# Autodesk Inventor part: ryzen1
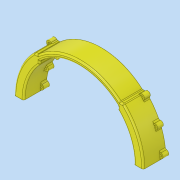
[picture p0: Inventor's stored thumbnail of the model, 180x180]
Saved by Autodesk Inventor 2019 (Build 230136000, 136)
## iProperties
Created: 2022-03
Part Number: ryzen1
Material: Типовые
Document SubType Name: Modeling
Designer: mitof
Density: 1 g/cm^3
Appearance: Желтый
Author: mitof
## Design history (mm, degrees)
sketch "Эскиз1"
  geometry: L1 (-80, 0)-(-74, 0); L2 (74, 0)-(80, 0); A1 r 80 centre (0, 0) between (80, 0) and (-80, 0); A2 r 74 centre (0, 0) between (74, 0) and (-74, 0); 1 further point
  constraints: 4 end point, 4 point on circle, 2 centre point, 2 point on line, 1 coincident, 1 horizontal
  dimensions: "d0" = 160 diameter of A1; "d1" = 6 radial gap between concentric circles of A1 A2
extrude "Выдавливание1" new body sketch "Эскиз1" distance "d2" = 26.5; taper "d3" = 0 deg
sketch "Эскиз2"
  geometry: L1 (-57.35, 60)-(-52.915, 60); L2 (-50.408, 54.176)-(-50.408, 50); L3 (52.915, 60)-(57.35, 60); L4 (50.408, 54.176)-(50.408, 50); L5 (-74, 0)-(-80, 0) reference; L6 (-83, 0)-(-80, 0); L7 (-80, 0)-(-74, 0); L8 (-74, 0)-(-71, 0); L9 (71, 0)-(74, 0); L10 (80, 0)-(74, 0) reference; L11 (80, 0)-(83, 0); A1 r 74 centre (0, 0) between (74, 0) and (-74, 0) reference; A2 r 80 centre (0, 0) between (80, 0) and (-80, 0) reference; A3 r 80 centre (0, 0) between (80, 0) and (-80, 0) reference; A4 r 74 centre (0, 0) between (74, 0) and (-74, 0) reference; A5 r 83 centre (0, 0) between (83, 0) and (57.35, 60); A6 r 83 centre (0, 0) between (-57.35, 60) and (-83, 0); A7 r 71 centre (0, 0) between (71, 0) and (50.408, 50); A8 r 71 centre (0, 0) between (-50.408, 50) and (-71, 0); 1 further point
  constraints: 18 end point, 12 point on circle, 5 collinear, 4 centre point, 2 horizontal, 2 perpendicular
  dimensions: "d6" = 50 vertical distance of point (0, 0) L2.end; "d7" = 60 vertical distance of point (0, 0) L1.start
extrude "Выдавливание2" join sketch "Эскиз2" stored distance "d8" = 35; taper "d9" = 0 deg
sketch "Эскиз3"
  geometry: L1 (-54.254, 50.617)-(-58.347, 54.439); L2 (54.254, 50.617)-(58.347, 54.439); L3 (-79.8, 0)-(-74.2, 0); L4 (-83, 0)-(-71, 0) reference; L5 (74.2, 0)-(79.8, 0); L6 (71, 0)-(83, 0) reference; A1 r 83 centre (0, 0) between (-57.35, 60) and (-83, 0) reference; A2 r 71 centre (0, 0) between (-50.408, 50) and (-71, 0) reference; A3 r 71 centre (0, 0) between (71, 0) and (50.408, 50) reference; A4 r 83 centre (0, 0) between (83, 0) and (57.35, 60) reference; A5 r 74.2 centre (0, 0) between (74.2, 0) and (54.254, 50.617); A6 r 79.8 centre (0, 0) between (79.8, 0) and (58.347, 54.439); A7 r 74.2 centre (0, 0) between (-54.254, 50.617) and (-74.2, 0); A8 r 79.8 centre (0, 0) between (-58.347, 54.439) and (-79.8, 0); 1 further point
  constraints: 8 end point, 8 point on circle, 4 centre point, 2 collinear
  dimensions: "d10" = 3.2 radial gap between concentric circles of A3 A5; "d11" = 3.2 radial gap between concentric circles of A4 A6; "d12" = 3.2 radial gap between concentric circles of A2 A7; "d13" = 3.2 radial gap between concentric circles of A1 A8
extrude "Выдавливание3" cut sketch "Эскиз3" distance "d14" = 21; taper "d15" = 0 deg
sketch "Эскиз4"
  geometry: L1 (54.254, 50.617)-(58.347, 54.439) reference; L2 (-58.347, 54.439)-(-54.254, 50.617) reference; A1 r 80 centre (0, 0) between (52.915, 60) and (-52.915, 60) reference; A2 r 74 centre (0, 0) between (50.408, 54.176) and (-50.408, 54.176) reference; A3 r 78 centre (0, 0) between (57.032, 53.211) and (-57.032, 53.211); A4 r 76 centre (0, 0) between (55.57, 51.846) and (-55.57, 51.846); 1 further point
  constraints: 4 point on circle, 4 point on line, 2 centre point
  dimensions: "d16" = 2 radial gap between concentric circles of A1 A3; "d17" = 2 radial gap between concentric circles of A2 A4
extrude "Выдавливание4" cut sketch "Эскиз4" distance "d18" = 5; taper "d19" = 0 deg
fillet "Сопряжение1" dims "d20" = 2
sketch "Эскиз5"
  geometry: C1 r 1.35 at (70, 5); C2 r 3.35 at (70, 5); 1 further point
  constraints: 2 centre point
  dimensions: "d21" = 2.7 diameter of C1; "d22" = 70 horizontal distance of C1.centre point (0, 0); "d23" = 5 vertical distance of point (0, 0) C1.centre; "d24" = 2 radial gap between concentric circles of C1 C2
extrude "Выдавливание5" join sketch "Эскиз5" distance "d25" = 5; taper "d26" = 0 deg
sketch "Эскиз6"
  geometry: C1 r 1.35 at (70, 5); A1 r 1.35 centre (70, 5) between (70.735, 6.133) and (70.888, 3.983) reference; 1 further point
  constraints: 1 centre point, 1 coincident
extrude "Выдавливание6" cut sketch "Эскиз6" distance "d27" = 5; taper "d28" = 0 deg
pattern_circular "Круговой массив1" dims angle "d30" = 40 deg
sketch "Эскиз7"
  geometry: C1 r 1.35 at (0, 73); A1 r 76 centre (0, 0) between (55.57, 51.846) and (-55.57, 51.846) reference; A2 r 3.35 centre (0, 73) between (-1.521, 75.985) and (1.521, 75.985); 1 further point
  constraints: 4 point on circle, 2 centre point
  dimensions: "d32" = 2.7 diameter of C1; "d33" = 73 distance of A1.centre C1.centre; "d34" = 2 radial gap between concentric circles of C1 A2
extrude "Выдавливание7" join sketch "Эскиз7" distance "d35" = 5; taper "d36" = 0 deg
sketch "Эскиз8"
  geometry: C1 r 1.35 at (0, 73); A1 r 1.35 centre (0, 73) between (-0.913, 73.994) and (0.913, 73.994) reference; 1 further point
  constraints: 1 centre point, 1 coincident
extrude "Выдавливание8" cut sketch "Эскиз8" distance "d37" = 5; taper "d38" = 0 deg
mirror "Зеркальное отражение1"
fillet "Сопряжение2" dims "d39" = 2
chamfer "Фаска1" distance "d40" = 8; stored, may be unused: second distance "d41" = 2, angle "d42" = 45 deg
chamfer "Фаска2" distance "d43" = 8; stored, may be unused: second distance "d44" = 2, angle "d45" = 45 deg
sketch "Эскиз11"
  geometry: C1 r 1.35 at (-70, 5) reference; C2 r 1.35 at (-64.068, 28.64) reference; C3 r 1.35 at (-50.409, 48.825) reference; C4 r 1.35 at (-83.5, 5); C5 r 1.35 at (-76.568, 33.925); C6 r 1.35 at (-59.809, 58.536); C7 r 3.35 at (-83.5, 5); C8 r 3.35 at (-76.568, 33.925); C9 r 3.35 at (-59.809, 58.536); A1 r 83 centre (0, 0) between (-57.938, 59.432) and (-83, 0) reference; 1 further point
  constraints: 6 centre point
  dimensions: "d46" = 2.7 diameter of C4; "d47" = 13.5 distance of C1.centre C4.centre; "d48" = 2.7 diameter of C5; "d49" = 12.5 horizontal distance of C2.centre C5.centre; "d50" = 2.7 diameter of C6; "d51" = 9.4 horizontal distance of C3.centre C6.centre; "d52" = 2 radial gap between concentric circles of C4 C7; "d53" = 2 radial gap between concentric circles of C5 C8; "d54" = 2 radial gap between concentric circles of C6 C9
extrude "Выдавливание9" join sketch "Эскиз11" distance "d55" = 5; taper "d56" = 0 deg
sketch "Эскиз12"
  geometry: C1 r 1.35 at (-83.5, 5); A1 r 1.35 centre (-83.5, 5) between (-82.773, 6.137) and (-82.914, 3.784) reference; A2 r 1.35 centre (-76.568, 33.925) between (-75.425, 34.643) and (-76.331, 32.596) reference; A3 r 1.35 centre (-59.809, 58.536) between (-58.503, 58.876) and (-60.122, 57.222) reference; 3 further points
  constraints: 3 coincident, 1 centre point, 6 other
extrude "Выдавливание10" cut sketch "Эскиз12" distance "d57" = 5; taper "d58" = 0 deg
sketch "Эскиз13"
  geometry: L1 (-83, 0)-(-79.8, 0) reference; L2 (-58.347, 54.439)-(-57.032, 53.211) reference; L3 (57.032, 53.211)-(58.347, 54.439) reference; L4 (79.8, 0)-(83, 0) reference; L5 (56.542, 60)-(53.666, 60) reference; L6 (-53.666, 60)-(-56.542, 60) reference; C1 r 1.35 at (0, 73) reference; C2 r 1.35 at (-76.568, 33.925) reference; C3 r 1.35 at (-83.5, 5) reference; C4 r 1.35 at (-59.809, 58.536) reference; A1 r 1.35 centre (0, 81) between (0.901, 79.995) and (-0.901, 79.995); A2 r 3.35 centre (0, 81) between (3.177, 79.937) and (-3.177, 79.937); A3 r 3.35 centre (-59.809, 58.536) between (-56.789, 59.985) and (-61.556, 55.677) reference; A4 r 83 centre (0, 0) between (-61.556, 55.677) and (-74.51, 36.569) reference; A5 r 3.35 centre (-76.568, 33.925) between (-74.51, 36.569) and (-77.143, 30.625) reference; A6 r 83 centre (0, 0) between (-77.143, 30.625) and (-82.592, 8.224) reference; A7 r 3.35 centre (-83.5, 5) between (-82.592, 8.224) and (-82.983, 1.69) reference; A8 r 83 centre (0, 0) between (-82.983, 1.69) and (-83, 0) reference; A9 r 79.8 centre (0, 0) between (-58.347, 54.439) and (-79.8, 0) reference; A10 r 78 centre (0, 0) between (57.032, 53.211) and (-57.032, 53.211) reference; A11 r 79.8 centre (0, 0) between (79.8, 0) and (58.347, 54.439) reference; A12 r 83 centre (0, 0) between (83, 0) and (57.938, 59.432) reference; A13 r 2 centre (56.542, 58) between (57.938, 59.432) and (56.542, 60) reference; A14 r 2 centre (53.666, 62) between (52.357, 60.488) and (53.666, 60) reference; A15 r 80 centre (0, 0) between (52.357, 60.488) and (-52.357, 60.488) reference; A16 r 2 centre (-53.666, 62) between (-53.666, 60) and (-52.357, 60.488) reference; A17 r 2 centre (-56.542, 58) between (-56.542, 60) and (-56.789, 59.985) reference; 1 further point
  constraints: 8 point on circle, 2 centre point
  dimensions: "d59" = 2.7 diameter of A1; "d60" = 8 distance of C1.centre A1.centre; "d61" = 2 radial gap between concentric circles of A1 A2
extrude "Выдавливание11" join sketch "Эскиз13" distance "d62" = 5; taper "d63" = 0 deg
sketch "Эскиз14"
  geometry: C1 r 1.35 at (0, 81); A1 r 1.35 centre (0, 81) between (0.901, 79.995) and (-0.901, 79.995) reference; 1 further point
  constraints: 1 centre point, 1 coincident
extrude "Выдавливание12" cut sketch "Эскиз14" distance "d64" = 5; taper "d65" = 0 deg
fillet "Сопряжение3" dims "d66" = 2
mirror "Зеркальное отражение2"
fillet "Сопряжение4" dims "d67" = 2
sketch "Эскиз15"
  geometry: L1 (71, 0)-(74.2, 0) reference; L2 (54.254, 50.617)-(55.57, 51.846) reference; L3 (-55.57, 51.846)-(-54.254, 50.617) reference; L4 (-74.2, 0)-(-71, 0) reference; L5 (55.732, 60)-(53.666, 60) reference; L6 (-53.666, 60)-(-55.732, 60) reference; L7 (-83, 0)-(-79.8, 0) reference; L8 (-58.347, 54.439)-(-57.032, 53.211) reference; L9 (57.032, 53.211)-(58.347, 54.439) reference; L10 (79.8, 0)-(83, 0) reference; C1 r 1.35 at (0, 73) reference; C2 r 1.35 at (64.068, 28.64) reference; C3 r 1.35 at (70, 5) reference; C4 r 1.35 at (50.409, 48.825) reference; C5 r 1.35 at (-70, 5) reference; C6 r 1.35 at (-50.409, 48.825) reference; C7 r 1.35 at (-64.068, 28.64) reference; C8 r 1.35 at (76.568, 33.925) reference; C9 r 1.35 at (0, 81) reference; C10 r 1.35 at (-76.568, 33.925) reference; C11 r 1.35 at (-83.5, 5) reference; C12 r 1.35 at (-59.809, 58.536) reference; C13 r 1.35 at (83.5, 5) reference; C14 r 1.35 at (59.809, 58.536) reference; A1 r 3.35 centre (-50.409, 48.825) between (-52.045, 45.902) and (-49.156, 51.932) reference; A2 r 2 centre (-48.408, 53.787) between (-50.393, 53.542) and (-49.156, 51.932) reference; A3 r 2 centre (-48.408, 53.298) between (-49.753, 54.778) and (-50.393, 53.542) reference; A4 r 74 centre (0, 0) between (-5.361, 73.806) and (-49.753, 54.778) reference; A5 r 2 centre (-5.216, 71.811) between (-3.266, 72.255) and (-5.361, 73.806) reference; A6 r 3.35 centre (0, 73) between (-3.266, 72.255) and (3.266, 72.255) reference; A7 r 2 centre (5.216, 71.811) between (5.361, 73.806) and (3.266, 72.255) reference; A8 r 74 centre (0, 0) between (49.753, 54.778) and (5.361, 73.806) reference; A9 r 2 centre (48.408, 53.298) between (50.393, 53.542) and (49.753, 54.778) reference; A10 r 2 centre (48.408, 53.787) between (49.156, 51.932) and (50.393, 53.542) reference; A11 r 3.35 centre (50.409, 48.825) between (49.156, 51.932) and (52.045, 45.902) reference; A12 r 2 centre (53.021, 44.156) between (54.558, 45.436) and (52.045, 45.902) reference; A13 r 71 centre (0, 0) between (62.465, 33.751) and (54.558, 45.436) reference; A14 r 2 centre (60.705, 32.801) between (61.962, 31.245) and (62.465, 33.751) reference; A15 r 3.35 centre (64.068, 28.64) between (61.962, 31.245) and (64.605, 25.333) reference; A16 r 2 centre (64.926, 23.359) between (66.808, 24.036) and (64.605, 25.333) reference; A17 r 71 centre (0, 0) between (70.241, 10.352) and (66.808, 24.036) reference; A18 r 2 centre (68.263, 10.06) between (68.912, 8.168) and (70.241, 10.352) reference; A19 r 3.35 centre (70, 5) between (68.912, 8.168) and (69.384, 1.707) reference; A20 r 2 centre (69.017, -0.259) between (71, 0) and (69.384, 1.707) reference; A21 r 74.2 centre (0, 0) between (74.2, 0) and (54.254, 50.617) reference; A22 r 76 centre (0, 0) between (55.57, 51.846) and (-55.57, 51.846) reference; A23 r 74.2 centre (0, 0) between (-54.254, 50.617) and (-74.2, 0) reference; A24 r 2 centre (-69.017, -0.259) between (-69.384, 1.707) and (-71, 0) reference; A25 r 3.35 centre (-70, 5) between (-69.384, 1.707) and (-68.912, 8.168) reference; A26 r 2 centre (-68.263, 10.06) between (-70.241, 10.352) and (-68.912, 8.168) reference; A27 r 71 centre (0, 0) between (-66.808, 24.036) and (-70.241, 10.352) reference; A28 r 2 centre (-64.926, 23.359) between (-64.605, 25.333) and (-66.808, 24.036) reference; A29 r 3.35 centre (-64.068, 28.64) between (-64.605, 25.333) and (-61.962, 31.245) reference; A30 r 2 centre (-60.705, 32.801) between (-62.465, 33.751) and (-61.962, 31.245) reference; A31 r 71 centre (0, 0) between (-54.558, 45.436) and (-62.465, 33.751) reference; A32 r 2 centre (-53.021, 44.156) between (-52.045, 45.902) and (-54.558, 45.436) reference; A33 r 2 centre (53.666, 62) between (52.357, 60.488) and (53.666, 60) reference; A34 r 80 centre (0, 0) between (52.357, 60.488) and (5.156, 79.834) reference; A35 r 2 centre (5.285, 81.829) between (3.309, 81.519) and (5.156, 79.834) reference; A36 r 3.35 centre (0, 81) between (3.309, 81.519) and (-3.309, 81.519) reference; A37 r 2 centre (-5.285, 81.829) between (-5.156, 79.834) and (-3.309, 81.519) reference; A38 r 80 centre (0, 0) between (-5.156, 79.834) and (-52.357, 60.488) reference; A39 r 2 centre (-53.666, 62) between (-53.666, 60) and (-52.357, 60.488) reference; A40 r 2 centre (-55.732, 62) between (-57.256, 60.705) and (-55.732, 60) reference; A41 r 3.35 centre (-59.809, 58.536) between (-57.256, 60.705) and (-62.613, 56.702) reference; A42 r 2 centre (-64.287, 55.608) between (-62.774, 54.299) and (-62.613, 56.702) reference; A43 r 83 centre (0, 0) between (-62.774, 54.299) and (-73.669, 38.235) reference; A44 r 2 centre (-75.444, 39.156) between (-75.864, 37.201) and (-73.669, 38.235) reference; A45 r 3.35 centre (-76.568, 33.925) between (-75.864, 37.201) and (-78.521, 31.204) reference; A46 r 2 centre (-79.687, 29.579) between (-77.812, 28.883) and (-78.521, 31.204) reference; A47 r 83 centre (0, 0) between (-77.812, 28.883) and (-82.391, 10.036) reference; A48 r 2 centre (-84.376, 10.278) between (-84.049, 8.305) and (-82.391, 10.036) reference; A49 r 3.35 centre (-83.5, 5) between (-84.049, 8.305) and (-84.436, 1.784) reference; A50 r 2 centre (-84.995, -0.137) between (-83, 0) and (-84.436, 1.784) reference; A51 r 79.8 centre (0, 0) between (-58.347, 54.439) and (-79.8, 0) reference; A52 r 78 centre (0, 0) between (57.032, 53.211) and (-57.032, 53.211) reference; A53 r 79.8 centre (0, 0) between (79.8, 0) and (58.347, 54.439) reference; A54 r 2 centre (84.995, -0.137) between (84.436, 1.784) and (83, 0) reference; A55 r 3.35 centre (83.5, 5) between (84.436, 1.784) and (84.049, 8.305) reference; A56 r 2 centre (84.376, 10.278) between (82.391, 10.036) and (84.049, 8.305) reference; A57 r 83 centre (0, 0) between (82.391, 10.036) and (77.812, 28.883) reference; A58 r 2 centre (79.687, 29.579) between (78.521, 31.204) and (77.812, 28.883) reference; A59 r 3.35 centre (76.568, 33.925) between (78.521, 31.204) and (75.864, 37.201) reference; A60 r 2 centre (75.444, 39.156) between (73.669, 38.235) and (75.864, 37.201) reference; A61 r 83 centre (0, 0) between (73.669, 38.235) and (62.774, 54.299) reference; A62 r 2 centre (64.287, 55.608) between (62.613, 56.702) and (62.774, 54.299) reference; A63 r 3.35 centre (59.809, 58.536) between (62.613, 56.702) and (57.256, 60.705) reference; A64 r 2 centre (55.732, 62) between (55.732, 60) and (57.256, 60.705) reference; 1 further point
extrude "Выдавливание13" join sketch "Эскиз15" distance "d68" = 2.4; taper "d69" = 0 deg
sketch "Эскиз16"
  geometry: L1 (79.8, 0)-(74.2, 0) reference; L2 (54.254, 50.617)-(58.347, 54.439) reference; L3 (55.812, 48.895)-(60.024, 52.585); L4 (57.316, 47.122)-(61.642, 50.678); A1 r 79.8 centre (0, 0) between (79.8, 0) and (58.347, 54.439) reference; A2 r 74.2 centre (0, 0) between (74.2, 0) and (54.254, 50.617) reference; A3 r 79.8 centre (0, 0) between (79.8, 0) and (58.347, 54.439) reference; 1 further point
  constraints: 4 end point, 4 point on circle
  dimensions: "d70" = 2.5 distance from line of L2 L3.end; "d71" = 2.5 distance from line of L3 L4.end
extrude "Выдавливание14" cut sketch "Эскиз16" distance "d72" = 1.2; taper "d73" = 0 deg
fillet "Сопряжение5" dims "d74" = 1.2
fillet "Сопряжение6" dims "d75" = 0.4
pattern_circular "Круговой массив2" dims angle "d77" = 37 deg
fillet "Сопряжение7" dims "d79" = 0.4
mirror "Зеркальное отражение3"
fillet "Сопряжение8" dims "d80" = 0.4
sketch "Эскиз18"
  geometry: L1 (55.732, 60)-(53.666, 60) reference; L2 (-53.666, 60)-(-55.732, 60) reference; L3 (-83, 0)-(-79.8, 0) reference; L4 (-58.347, 54.439)-(-57.032, 53.211) reference; L5 (57.032, 53.211)-(58.347, 54.439) reference; L6 (79.8, 0)-(83, 0) reference; L7 (71, 0)-(74.2, 0) reference; L8 (54.254, 50.617)-(55.57, 51.846) reference; L9 (-55.57, 51.846)-(-54.254, 50.617) reference; L10 (-74.2, 0)-(-71, 0) reference; L11 (-74.6, 0)-(-74.2, 0); L12 (-79.4, 0)-(-79.8, 0); L13 (-81, 0)-(-73, 0) reference; L14 (-58.347, 54.439)-(-54.254, 50.617) reference; L15 (-54.547, 50.89)-(-54.254, 50.617); L16 (-58.055, 54.166)-(-58.347, 54.439); C1 r 1.35 at (59.809, 58.536) reference; C2 r 1.35 at (83.5, 5) reference; C3 r 1.35 at (-59.809, 58.536) reference; C4 r 1.35 at (-83.5, 5) reference; C5 r 1.35 at (-76.568, 33.925) reference; C6 r 1.35 at (0, 81) reference; C7 r 1.35 at (76.568, 33.925) reference; C8 r 1.35 at (-64.068, 28.64) reference; C9 r 1.35 at (-50.409, 48.825) reference; C10 r 1.35 at (-70, 5) reference; C11 r 1.35 at (50.409, 48.825) reference; C12 r 1.35 at (70, 5) reference; C13 r 1.35 at (64.068, 28.64) reference; C14 r 1.35 at (0, 73) reference; A1 r 2 centre (53.666, 62) between (52.357, 60.488) and (53.666, 60) reference; A2 r 80 centre (0, 0) between (52.357, 60.488) and (5.156, 79.834) reference; A3 r 2 centre (5.285, 81.829) between (3.309, 81.519) and (5.156, 79.834) reference; A4 r 3.35 centre (0, 81) between (3.309, 81.519) and (-3.309, 81.519) reference; A5 r 2 centre (-5.285, 81.829) between (-5.156, 79.834) and (-3.309, 81.519) reference; A6 r 80 centre (0, 0) between (-5.156, 79.834) and (-52.357, 60.488) reference; A7 r 2 centre (-53.666, 62) between (-53.666, 60) and (-52.357, 60.488) reference; A8 r 2 centre (-55.732, 62) between (-57.256, 60.705) and (-55.732, 60) reference; A9 r 3.35 centre (-59.809, 58.536) between (-57.256, 60.705) and (-62.613, 56.702) reference; A10 r 2 centre (-64.287, 55.608) between (-62.774, 54.299) and (-62.613, 56.702) reference; A11 r 83 centre (0, 0) between (-62.774, 54.299) and (-73.669, 38.235) reference; A12 r 2 centre (-75.444, 39.156) between (-75.864, 37.201) and (-73.669, 38.235) reference; A13 r 3.35 centre (-76.568, 33.925) between (-75.864, 37.201) and (-78.521, 31.204) reference; A14 r 2 centre (-79.687, 29.579) between (-77.812, 28.883) and (-78.521, 31.204) reference; A15 r 83 centre (0, 0) between (-77.812, 28.883) and (-82.391, 10.036) reference; A16 r 2 centre (-84.376, 10.278) between (-84.049, 8.305) and (-82.391, 10.036) reference; A17 r 3.35 centre (-83.5, 5) between (-84.049, 8.305) and (-84.436, 1.784) reference; A18 r 2 centre (-84.995, -0.137) between (-83, 0) and (-84.436, 1.784) reference; A19 r 79.8 centre (0, 0) between (-58.347, 54.439) and (-79.8, 0) reference; A20 r 78 centre (0, 0) between (57.032, 53.211) and (-57.032, 53.211) reference; A21 r 79.8 centre (0, 0) between (79.8, 0) and (58.347, 54.439) reference; A22 r 2 centre (84.995, -0.137) between (84.436, 1.784) and (83, 0) reference; A23 r 3.35 centre (83.5, 5) between (84.436, 1.784) and (84.049, 8.305) reference; A24 r 2 centre (84.376, 10.278) between (82.391, 10.036) and (84.049, 8.305) reference; A25 r 83 centre (0, 0) between (82.391, 10.036) and (77.812, 28.883) reference; A26 r 2 centre (79.687, 29.579) between (78.521, 31.204) and (77.812, 28.883) reference; A27 r 3.35 centre (76.568, 33.925) between (78.521, 31.204) and (75.864, 37.201) reference; A28 r 2 centre (75.444, 39.156) between (73.669, 38.235) and (75.864, 37.201) reference; A29 r 83 centre (0, 0) between (73.669, 38.235) and (62.774, 54.299) reference; A30 r 2 centre (64.287, 55.608) between (62.613, 56.702) and (62.774, 54.299) reference; A31 r 3.35 centre (59.809, 58.536) between (62.613, 56.702) and (57.256, 60.705) reference; A32 r 2 centre (55.732, 62) between (55.732, 60) and (57.256, 60.705) reference; A33 r 3.35 centre (-50.409, 48.825) between (-52.045, 45.902) and (-49.156, 51.932) reference; A34 r 2 centre (-48.408, 53.787) between (-50.393, 53.542) and (-49.156, 51.932) reference; A35 r 2 centre (-48.408, 53.298) between (-49.753, 54.778) and (-50.393, 53.542) reference; A36 r 74 centre (0, 0) between (-5.361, 73.806) and (-49.753, 54.778) reference; A37 r 2 centre (-5.216, 71.811) between (-3.266, 72.255) and (-5.361, 73.806) reference; A38 r 3.35 centre (0, 73) between (-3.266, 72.255) and (3.266, 72.255) reference; A39 r 2 centre (5.216, 71.811) between (5.361, 73.806) and (3.266, 72.255) reference; A40 r 74 centre (0, 0) between (49.753, 54.778) and (5.361, 73.806) reference; A41 r 2 centre (48.408, 53.298) between (50.393, 53.542) and (49.753, 54.778) reference; A42 r 2 centre (48.408, 53.787) between (49.156, 51.932) and (50.393, 53.542) reference; A43 r 3.35 centre (50.409, 48.825) between (49.156, 51.932) and (52.045, 45.902) reference; A44 r 2 centre (53.021, 44.156) between (54.558, 45.436) and (52.045, 45.902) reference; A45 r 71 centre (0, 0) between (62.465, 33.751) and (54.558, 45.436) reference; A46 r 2 centre (60.705, 32.801) between (61.962, 31.245) and (62.465, 33.751) reference; A47 r 3.35 centre (64.068, 28.64) between (61.962, 31.245) and (64.605, 25.333) reference; A48 r 2 centre (64.926, 23.359) between (66.808, 24.036) and (64.605, 25.333) reference; A49 r 71 centre (0, 0) between (70.241, 10.352) and (66.808, 24.036) reference; A50 r 2 centre (68.263, 10.06) between (68.912, 8.168) and (70.241, 10.352) reference; A51 r 3.35 centre (70, 5) between (68.912, 8.168) and (69.384, 1.707) reference; A52 r 2 centre (69.017, -0.259) between (71, 0) and (69.384, 1.707) reference; A53 r 74.2 centre (0, 0) between (74.2, 0) and (54.254, 50.617) reference; A54 r 76 centre (0, 0) between (55.57, 51.846) and (-55.57, 51.846) reference; A55 r 74.2 centre (0, 0) between (-54.254, 50.617) and (-74.2, 0) reference; A56 r 2 centre (-69.017, -0.259) between (-69.384, 1.707) and (-71, 0) reference; A57 r 3.35 centre (-70, 5) between (-69.384, 1.707) and (-68.912, 8.168) reference; A58 r 2 centre (-68.263, 10.06) between (-70.241, 10.352) and (-68.912, 8.168) reference; A59 r 71 centre (0, 0) between (-66.808, 24.036) and (-70.241, 10.352) reference; A60 r 2 centre (-64.926, 23.359) between (-64.605, 25.333) and (-66.808, 24.036) reference; A61 r 3.35 centre (-64.068, 28.64) between (-64.605, 25.333) and (-61.962, 31.245) reference; A62 r 2 centre (-60.705, 32.801) between (-62.465, 33.751) and (-61.962, 31.245) reference; A63 r 71 centre (0, 0) between (-54.558, 45.436) and (-62.465, 33.751) reference; A64 r 2 centre (-53.021, 44.156) between (-52.045, 45.902) and (-54.558, 45.436) reference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; 1 further point
  constraints: 8 end point, 4 point on circle, 3 collinear, 2 centre point, 1 horizontal
  dimensions: "d81" = 0.4 radial gap between concentric circles of A19 A67; "d82" = 0.4 radial gap between concentric circles of A55 A68
extrude "Выдавливание15" join sketch "Эскиз18" stored distance "d83" = 10; taper "d84" = 0 deg
sketch "Эскиз19"
  geometry: L1 (55.732, 60)-(53.666, 60) reference; L2 (-53.666, 60)-(-55.732, 60) reference; L3 (-83, 0)-(-79.4, 0) reference; L4 (-58.055, 54.166)-(-57.032, 53.211) reference; L5 (57.032, 53.211)-(58.347, 54.439) reference; L6 (79.8, 0)-(83, 0) reference; L7 (71, 0)-(74.2, 0) reference; L8 (54.254, 50.617)-(55.57, 51.846) reference; L9 (-55.57, 51.846)-(-54.547, 50.89) reference; L10 (-74.6, 0)-(-71, 0) reference; L11 (79.4, 0)-(79.8, 0); L12 (57.032, 53.211)-(58.347, 54.439) reference; L13 (58.055, 54.166)-(58.347, 54.439); L14 (54.254, 50.617)-(55.57, 51.846) reference; L15 (58.62, 54.147)-(58.619, 54.146); L16 (79.799, 0.4)-(79.8, 0.4); L17 (58.619, 54.146)-(58.347, 54.439); L18 (79.8, 0.4)-(79.8, 0); L19 (74.2, 0)-(74.6, 0); L20 (54.547, 50.89)-(54.254, 50.617); C1 r 1.35 at (59.809, 58.536) reference; C2 r 1.35 at (83.5, 5) reference; C3 r 1.35 at (-59.809, 58.536) reference; C4 r 1.35 at (-83.5, 5) reference; C5 r 1.35 at (-76.568, 33.925) reference; C6 r 1.35 at (0, 81) reference; C7 r 1.35 at (76.568, 33.925) reference; C8 r 1.35 at (-64.068, 28.64) reference; C9 r 1.35 at (-50.409, 48.825) reference; C10 r 1.35 at (-70, 5) reference; C11 r 1.35 at (50.409, 48.825) reference; C12 r 1.35 at (70, 5) reference; C13 r 1.35 at (64.068, 28.64) reference; C14 r 1.35 at (0, 73) reference; A1 r 79.8 centre (0, 0) between (79.8, 0) and (58.347, 54.439) reference; A2 r 74.2 centre (0, 0) between (74.2, 0) and (54.254, 50.617) reference; A3 r 2 centre (53.666, 62) between (52.357, 60.488) and (53.666, 60) reference; A4 r 80 centre (0, 0) between (52.357, 60.488) and (5.156, 79.834) reference; A5 r 2 centre (5.285, 81.829) between (3.309, 81.519) and (5.156, 79.834) reference; A6 r 3.35 centre (0, 81) between (3.309, 81.519) and (-3.309, 81.519) reference; A7 r 2 centre (-5.285, 81.829) between (-5.156, 79.834) and (-3.309, 81.519) reference; A8 r 80 centre (0, 0) between (-5.156, 79.834) and (-52.357, 60.488) reference; A9 r 2 centre (-53.666, 62) between (-53.666, 60) and (-52.357, 60.488) reference; A10 r 2 centre (-55.732, 62) between (-57.256, 60.705) and (-55.732, 60) reference; A11 r 3.35 centre (-59.809, 58.536) between (-57.256, 60.705) and (-62.613, 56.702) reference; A12 r 2 centre (-64.287, 55.608) between (-62.774, 54.299) and (-62.613, 56.702) reference; A13 r 83 centre (0, 0) between (-62.774, 54.299) and (-73.669, 38.235) reference; A14 r 2 centre (-75.444, 39.156) between (-75.864, 37.201) and (-73.669, 38.235) reference; A15 r 3.35 centre (-76.568, 33.925) between (-75.864, 37.201) and (-78.521, 31.204) reference; A16 r 2 centre (-79.687, 29.579) between (-77.812, 28.883) and (-78.521, 31.204) reference; A17 r 83 centre (0, 0) between (-77.812, 28.883) and (-82.391, 10.036) reference; A18 r 2 centre (-84.376, 10.278) between (-84.049, 8.305) and (-82.391, 10.036) reference; A19 r 3.35 centre (-83.5, 5) between (-84.049, 8.305) and (-84.436, 1.784) reference; A20 r 2 centre (-84.995, -0.137) between (-83, 0) and (-84.436, 1.784) reference; A21 r 79.4 centre (0, 0) between (-58.055, 54.166) and (-79.4, 0) reference; A22 r 78 centre (0, 0) between (57.032, 53.211) and (-57.032, 53.211) reference; A23 r 79.8 centre (0, 0) between (79.8, 0) and (58.347, 54.439) reference; A24 r 2 centre (84.995, -0.137) between (84.436, 1.784) and (83, 0) reference; A25 r 3.35 centre (83.5, 5) between (84.436, 1.784) and (84.049, 8.305) reference; A26 r 2 centre (84.376, 10.278) between (82.391, 10.036) and (84.049, 8.305) reference; A27 r 83 centre (0, 0) between (82.391, 10.036) and (77.812, 28.883) reference; A28 r 2 centre (79.687, 29.579) between (78.521, 31.204) and (77.812, 28.883) reference; A29 r 3.35 centre (76.568, 33.925) between (78.521, 31.204) and (75.864, 37.201) reference; A30 r 2 centre (75.444, 39.156) between (73.669, 38.235) and (75.864, 37.201) reference; A31 r 83 centre (0, 0) between (73.669, 38.235) and (62.774, 54.299) reference; A32 r 2 centre (64.287, 55.608) between (62.613, 56.702) and (62.774, 54.299) reference; A33 r 3.35 centre (59.809, 58.536) between (62.613, 56.702) and (57.256, 60.705) reference; A34 r 2 centre (55.732, 62) between (55.732, 60) and (57.256, 60.705) reference; A35 r 3.35 centre (-50.409, 48.825) between (-52.045, 45.902) and (-49.156, 51.932) reference; A36 r 2 centre (-48.408, 53.787) between (-50.393, 53.542) and (-49.156, 51.932) reference; A37 r 2 centre (-48.408, 53.298) between (-49.753, 54.778) and (-50.393, 53.542) reference; A38 r 74 centre (0, 0) between (-5.361, 73.806) and (-49.753, 54.778) reference; A39 r 2 centre (-5.216, 71.811) between (-3.266, 72.255) and (-5.361, 73.806) reference; A40 r 3.35 centre (0, 73) between (-3.266, 72.255) and (3.266, 72.255) reference; A41 r 2 centre (5.216, 71.811) between (5.361, 73.806) and (3.266, 72.255) reference; A42 r 74 centre (0, 0) between (49.753, 54.778) and (5.361, 73.806) reference; A43 r 2 centre (48.408, 53.298) between (50.393, 53.542) and (49.753, 54.778) reference; A44 r 2 centre (48.408, 53.787) between (49.156, 51.932) and (50.393, 53.542) reference; A45 r 3.35 centre (50.409, 48.825) between (49.156, 51.932) and (52.045, 45.902) reference; A46 r 2 centre (53.021, 44.156) between (54.558, 45.436) and (52.045, 45.902) reference; A47 r 71 centre (0, 0) between (62.465, 33.751) and (54.558, 45.436) reference; A48 r 2 centre (60.705, 32.801) between (61.962, 31.245) and (62.465, 33.751) reference; A49 r 3.35 centre (64.068, 28.64) between (61.962, 31.245) and (64.605, 25.333) reference; A50 r 2 centre (64.926, 23.359) between (66.808, 24.036) and (64.605, 25.333) reference; A51 r 71 centre (0, 0) between (70.241, 10.352) and (66.808, 24.036) reference; A52 r 2 centre (68.263, 10.06) between (68.912, 8.168) and (70.241, 10.352) reference; A53 r 3.35 centre (70, 5) between (68.912, 8.168) and (69.384, 1.707) reference; A54 r 2 centre (69.017, -0.259) between (71, 0) and (69.384, 1.707) reference; A55 r 74.2 centre (0, 0) between (74.2, 0) and (54.254, 50.617) reference; A56 r 76 centre (0, 0) between (55.57, 51.846) and (-55.57, 51.846) reference; A57 r 74.6 centre (0, 0) between (-54.547, 50.89) and (-74.6, 0) reference; A58 r 2 centre (-69.017, -0.259) between (-69.384, 1.707) and (-71, 0) reference; A59 r 3.35 centre (-70, 5) between (-69.384, 1.707) and (-68.912, 8.168) reference; A60 r 2 centre (-68.263, 10.06) between (-70.241, 10.352) and (-68.912, 8.168) reference; A61 r 71 centre (0, 0) between (-66.808, 24.036) and (-70.241, 10.352) reference; A62 r 2 centre (-64.926, 23.359) between (-64.605, 25.333) and (-66.808, 24.036) reference; A63 r 3.35 centre (-64.068, 28.64) between (-64.605, 25.333) and (-61.962, 31.245) reference; A64 r 2 centre (-60.705, 32.801) between (-62.465, 33.751) and (-61.962, 31.245) reference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; 3 further points
  constraints: 16 end point, 9 point on circle, 4 centre point, 2 horizontal, 2 tangent, 1 collinear, 1 parallel, 1 point on line, 1 vertical, 3 other
  dimensions: "d85" = 0.4 radial gap between concentric circles of A2 A67; "d86" = 0.4 radial gap between concentric circles of A1 A68; "d87" = 0.4 radial gap between concentric circles of A68 A69; "d88" = 0.4 radial gap between concentric circles of A67 A70
extrude "Выдавливание16" join sketch "Эскиз19" stored distance "d89" = 10; taper "d90" = 0 deg
sketch "Эскиз21"
  geometry: L1 (55.732, 60)-(53.666, 60) reference; L2 (-53.666, 60)-(-55.732, 60) reference; L3 (-83, 0)-(-79.4, 0) reference; L4 (-58.055, 54.166)-(-57.032, 53.211) reference; L5 (57.032, 53.211)-(58.055, 54.166) reference; L6 (79.4, 0)-(83, 0) reference; L7 (54.547, 50.89)-(55.57, 51.846) reference; L8 (-55.57, 51.846)-(-54.547, 50.89) reference; L9 (-74.6, 0)-(-71, 0) reference; L10 (71, 0)-(74.6, 0) reference; C1 r 1.35 at (59.809, 58.536) reference; C2 r 1.35 at (83.5, 5) reference; C3 r 1.35 at (-59.809, 58.536) reference; C4 r 1.35 at (-83.5, 5) reference; C5 r 1.35 at (-76.568, 33.925) reference; C6 r 1.35 at (0, 81) reference; C7 r 1.35 at (76.568, 33.925) reference; C8 r 1.35 at (-64.068, 28.64) reference; C9 r 1.35 at (-50.409, 48.825) reference; C10 r 1.35 at (-70, 5) reference; C11 r 1.35 at (50.409, 48.825) reference; C12 r 1.35 at (70, 5) reference; C13 r 1.35 at (64.068, 28.64) reference; C14 r 1.35 at (0, 73) reference; A1 r 2 centre (53.666, 62) between (52.357, 60.488) and (53.666, 60) reference; A2 r 80 centre (0, 0) between (52.357, 60.488) and (5.156, 79.834) reference; A3 r 2 centre (5.285, 81.829) between (3.309, 81.519) and (5.156, 79.834) reference; A4 r 3.35 centre (0, 81) between (3.309, 81.519) and (-3.309, 81.519) reference; A5 r 2 centre (-5.285, 81.829) between (-5.156, 79.834) and (-3.309, 81.519) reference; A6 r 80 centre (0, 0) between (-5.156, 79.834) and (-52.357, 60.488) reference; A7 r 2 centre (-53.666, 62) between (-53.666, 60) and (-52.357, 60.488) reference; A8 r 2 centre (-55.732, 62) between (-57.256, 60.705) and (-55.732, 60) reference; A9 r 3.35 centre (-59.809, 58.536) between (-57.256, 60.705) and (-62.613, 56.702) reference; A10 r 2 centre (-64.287, 55.608) between (-62.774, 54.299) and (-62.613, 56.702) reference; A11 r 83 centre (0, 0) between (-62.774, 54.299) and (-73.669, 38.235) reference; A12 r 2 centre (-75.444, 39.156) between (-75.864, 37.201) and (-73.669, 38.235) reference; A13 r 3.35 centre (-76.568, 33.925) between (-75.864, 37.201) and (-78.521, 31.204) reference; A14 r 2 centre (-79.687, 29.579) between (-77.812, 28.883) and (-78.521, 31.204) reference; A15 r 83 centre (0, 0) between (-77.812, 28.883) and (-82.391, 10.036) reference; A16 r 2 centre (-84.376, 10.278) between (-84.049, 8.305) and (-82.391, 10.036) reference; A17 r 3.35 centre (-83.5, 5) between (-84.049, 8.305) and (-84.436, 1.784) reference; A18 r 2 centre (-84.995, -0.137) between (-83, 0) and (-84.436, 1.784) reference; A19 r 79.4 centre (0, 0) between (-58.055, 54.166) and (-79.4, 0) reference; A20 r 78 centre (0, 0) between (57.032, 53.211) and (-57.032, 53.211) reference; A21 r 79.4 centre (0, 0) between (79.4, 0) and (58.055, 54.166) reference; A22 r 2 centre (84.995, -0.137) between (84.436, 1.784) and (83, 0) reference; A23 r 3.35 centre (83.5, 5) between (84.436, 1.784) and (84.049, 8.305) reference; A24 r 2 centre (84.376, 10.278) between (82.391, 10.036) and (84.049, 8.305) reference; A25 r 83 centre (0, 0) between (82.391, 10.036) and (77.812, 28.883) reference; A26 r 2 centre (79.687, 29.579) between (78.521, 31.204) and (77.812, 28.883) reference; A27 r 3.35 centre (76.568, 33.925) between (78.521, 31.204) and (75.864, 37.201) reference; A28 r 2 centre (75.444, 39.156) between (73.669, 38.235) and (75.864, 37.201) reference; A29 r 83 centre (0, 0) between (73.669, 38.235) and (62.774, 54.299) reference; A30 r 2 centre (64.287, 55.608) between (62.613, 56.702) and (62.774, 54.299) reference; A31 r 3.35 centre (59.809, 58.536) between (62.613, 56.702) and (57.256, 60.705) reference; A32 r 2 centre (55.732, 62) between (55.732, 60) and (57.256, 60.705) reference; A33 r 76 centre (0, 0) between (55.57, 51.846) and (-55.57, 51.846) reference; A34 r 74.6 centre (0, 0) between (-54.547, 50.89) and (-74.6, 0) reference; A35 r 2 centre (-69.017, -0.259) between (-69.384, 1.707) and (-71, 0) reference; A36 r 3.35 centre (-70, 5) between (-69.384, 1.707) and (-68.912, 8.168) reference; A37 r 2 centre (-68.263, 10.06) between (-70.241, 10.352) and (-68.912, 8.168) reference; A38 r 71 centre (0, 0) between (-66.808, 24.036) and (-70.241, 10.352) reference; A39 r 2 centre (-64.926, 23.359) between (-64.605, 25.333) and (-66.808, 24.036) reference; A40 r 3.35 centre (-64.068, 28.64) between (-64.605, 25.333) and (-61.962, 31.245) reference; A41 r 2 centre (-60.705, 32.801) between (-62.465, 33.751) and (-61.962, 31.245) reference; A42 r 71 centre (0, 0) between (-54.558, 45.436) and (-62.465, 33.751) reference; A43 r 2 centre (-53.021, 44.156) between (-52.045, 45.902) and (-54.558, 45.436) reference; A44 r 3.35 centre (-50.409, 48.825) between (-52.045, 45.902) and (-49.156, 51.932) reference; A45 r 2 centre (-48.408, 53.787) between (-50.393, 53.542) and (-49.156, 51.932) reference; A46 r 2 centre (-48.408, 53.298) between (-49.753, 54.778) and (-50.393, 53.542) reference; A47 r 74 centre (0, 0) between (-5.361, 73.806) and (-49.753, 54.778) reference; A48 r 2 centre (-5.216, 71.811) between (-3.266, 72.255) and (-5.361, 73.806) reference; A49 r 3.35 centre (0, 73) between (-3.266, 72.255) and (3.266, 72.255) reference; A50 r 2 centre (5.216, 71.811) between (5.361, 73.806) and (3.266, 72.255) reference; A51 r 74 centre (0, 0) between (49.753, 54.778) and (5.361, 73.806) reference; A52 r 2 centre (48.408, 53.298) between (50.393, 53.542) and (49.753, 54.778) reference; A53 r 2 centre (48.408, 53.787) between (49.156, 51.932) and (50.393, 53.542) reference; A54 r 3.35 centre (50.409, 48.825) between (49.156, 51.932) and (52.045, 45.902) reference; A55 r 2 centre (53.021, 44.156) between (54.558, 45.436) and (52.045, 45.902) reference; A56 r 71 centre (0, 0) between (62.465, 33.751) and (54.558, 45.436) reference; A57 r 2 centre (60.705, 32.801) between (61.962, 31.245) and (62.465, 33.751) reference; A58 r 3.35 centre (64.068, 28.64) between (61.962, 31.245) and (64.605, 25.333) reference; A59 r 2 centre (64.926, 23.359) between (66.808, 24.036) and (64.605, 25.333) reference; A60 r 71 centre (0, 0) between (70.241, 10.352) and (66.808, 24.036) reference; A61 r 2 centre (68.263, 10.06) between (68.912, 8.168) and (70.241, 10.352) reference; A62 r 3.35 centre (70, 5) between (68.912, 8.168) and (69.384, 1.707) reference; A63 r 2 centre (69.017, -0.259) between (71, 0) and (69.384, 1.707) reference; A64 r 74.6 centre (0, 0) between (74.6, 0) and (54.547, 50.89) reference; 1 further point
extrude "Выдавливание17" join sketch "Эскиз21" stored distance "d91" = 12; taper "d92" = 0 deg
sketch "Эскиз22"
  geometry: L1 (55.732, 60)-(53.666, 60) reference; L2 (-53.666, 60)-(-55.732, 60) reference; L3 (-83, 0)-(-79.4, 0) reference; L4 (-58.055, 54.166)-(-57.032, 53.211) reference; L5 (57.032, 53.211)-(58.055, 54.166) reference; L6 (79.4, 0)-(83, 0) reference; L7 (54.547, 50.89)-(55.57, 51.846) reference; L8 (-55.57, 51.846)-(-54.547, 50.89) reference; L9 (-74.6, 0)-(-71, 0) reference; L10 (71, 0)-(74.6, 0) reference; C1 r 1.35 at (59.809, 58.536) reference; C2 r 1.35 at (83.5, 5) reference; C3 r 1.35 at (-59.809, 58.536) reference; C4 r 1.35 at (-83.5, 5) reference; C5 r 1.35 at (-76.568, 33.925) reference; C6 r 1.35 at (76.568, 33.925) reference; C7 r 1.35 at (-64.068, 28.64) reference; C8 r 1.35 at (-50.409, 48.825) reference; C9 r 1.35 at (-70, 5) reference; C10 r 1.35 at (50.409, 48.825) reference; C11 r 1.35 at (70, 5) reference; C12 r 1.35 at (64.068, 28.64) reference; A1 r 2 centre (53.666, 62) between (52.357, 60.488) and (53.666, 60) reference; A2 r 80 centre (0, 0) between (52.357, 60.488) and (5.156, 79.834) reference; A3 r 2 centre (5.285, 81.829) between (3.309, 81.519) and (5.156, 79.834) reference; A4 r 3.35 centre (0, 81) between (3.309, 81.519) and (-3.309, 81.519) reference; A5 r 2 centre (-5.285, 81.829) between (-5.156, 79.834) and (-3.309, 81.519) reference; A6 r 80 centre (0, 0) between (-5.156, 79.834) and (-52.357, 60.488) reference; A7 r 2 centre (-53.666, 62) between (-53.666, 60) and (-52.357, 60.488) reference; A8 r 2 centre (-55.732, 62) between (-57.256, 60.705) and (-55.732, 60) reference; A9 r 3.35 centre (-59.809, 58.536) between (-57.256, 60.705) and (-62.613, 56.702) reference; A10 r 2 centre (-64.287, 55.608) between (-62.774, 54.299) and (-62.613, 56.702) reference; A11 r 83 centre (0, 0) between (-62.774, 54.299) and (-73.669, 38.235) reference; A12 r 2 centre (-75.444, 39.156) between (-75.864, 37.201) and (-73.669, 38.235) reference; A13 r 3.35 centre (-76.568, 33.925) between (-75.864, 37.201) and (-78.521, 31.204) reference; A14 r 2 centre (-79.687, 29.579) between (-77.812, 28.883) and (-78.521, 31.204) reference; A15 r 83 centre (0, 0) between (-77.812, 28.883) and (-82.391, 10.036) reference; A16 r 2 centre (-84.376, 10.278) between (-84.049, 8.305) and (-82.391, 10.036) reference; A17 r 3.35 centre (-83.5, 5) between (-84.049, 8.305) and (-84.436, 1.784) reference; A18 r 2 centre (-84.995, -0.137) between (-83, 0) and (-84.436, 1.784) reference; A19 r 79.4 centre (0, 0) between (-58.055, 54.166) and (-79.4, 0) reference; A20 r 78 centre (0, 0) between (57.032, 53.211) and (-57.032, 53.211) reference; A21 r 79.4 centre (0, 0) between (79.4, 0) and (58.055, 54.166) reference; A22 r 2 centre (84.995, -0.137) between (84.436, 1.784) and (83, 0) reference; A23 r 3.35 centre (83.5, 5) between (84.436, 1.784) and (84.049, 8.305) reference; A24 r 2 centre (84.376, 10.278) between (82.391, 10.036) and (84.049, 8.305) reference; A25 r 83 centre (0, 0) between (82.391, 10.036) and (77.812, 28.883) reference; A26 r 2 centre (79.687, 29.579) between (78.521, 31.204) and (77.812, 28.883) reference; A27 r 3.35 centre (76.568, 33.925) between (78.521, 31.204) and (75.864, 37.201) reference; A28 r 2 centre (75.444, 39.156) between (73.669, 38.235) and (75.864, 37.201) reference; A29 r 83 centre (0, 0) between (73.669, 38.235) and (62.774, 54.299) reference; A30 r 2 centre (64.287, 55.608) between (62.613, 56.702) and (62.774, 54.299) reference; A31 r 3.35 centre (59.809, 58.536) between (62.613, 56.702) and (57.256, 60.705) reference; A32 r 2 centre (55.732, 62) between (55.732, 60) and (57.256, 60.705) reference; A33 r 76 centre (0, 0) between (55.57, 51.846) and (-55.57, 51.846) reference; A34 r 74.6 centre (0, 0) between (-54.547, 50.89) and (-74.6, 0) reference; A35 r 2 centre (-69.017, -0.259) between (-69.384, 1.707) and (-71, 0) reference; A36 r 3.35 centre (-70, 5) between (-69.384, 1.707) and (-68.912, 8.168) reference; A37 r 2 centre (-68.263, 10.06) between (-70.241, 10.352) and (-68.912, 8.168) reference; A38 r 71 centre (0, 0) between (-66.808, 24.036) and (-70.241, 10.352) reference; A39 r 2 centre (-64.926, 23.359) between (-64.605, 25.333) and (-66.808, 24.036) reference; A40 r 3.35 centre (-64.068, 28.64) between (-64.605, 25.333) and (-61.962, 31.245) reference; A41 r 2 centre (-60.705, 32.801) between (-62.465, 33.751) and (-61.962, 31.245) reference; A42 r 71 centre (0, 0) between (-54.558, 45.436) and (-62.465, 33.751) reference; A43 r 2 centre (-53.021, 44.156) between (-52.045, 45.902) and (-54.558, 45.436) reference; A44 r 3.35 centre (-50.409, 48.825) between (-52.045, 45.902) and (-49.156, 51.932) reference; A45 r 2 centre (-48.408, 53.787) between (-50.393, 53.542) and (-49.156, 51.932) reference; A46 r 2 centre (-48.408, 53.298) between (-49.753, 54.778) and (-50.393, 53.542) reference; A47 r 74 centre (0, 0) between (-5.361, 73.806) and (-49.753, 54.778) reference; A48 r 2 centre (-5.216, 71.811) between (-3.266, 72.255) and (-5.361, 73.806) reference; A49 r 3.35 centre (0, 73) between (-3.266, 72.255) and (3.266, 72.255) reference; A50 r 2 centre (5.216, 71.811) between (5.361, 73.806) and (3.266, 72.255) reference; A51 r 74 centre (0, 0) between (49.753, 54.778) and (5.361, 73.806) reference; A52 r 2 centre (48.408, 53.298) between (50.393, 53.542) and (49.753, 54.778) reference; A53 r 2 centre (48.408, 53.787) between (49.156, 51.932) and (50.393, 53.542) reference; A54 r 3.35 centre (50.409, 48.825) between (49.156, 51.932) and (52.045, 45.902) reference; A55 r 2 centre (53.021, 44.156) between (54.558, 45.436) and (52.045, 45.902) reference; A56 r 71 centre (0, 0) between (62.465, 33.751) and (54.558, 45.436) reference; A57 r 2 centre (60.705, 32.801) between (61.962, 31.245) and (62.465, 33.751) reference; A58 r 3.35 centre (64.068, 28.64) between (61.962, 31.245) and (64.605, 25.333) reference; A59 r 2 centre (64.926, 23.359) between (66.808, 24.036) and (64.605, 25.333) reference; A60 r 71 centre (0, 0) between (70.241, 10.352) and (66.808, 24.036) reference; A61 r 2 centre (68.263, 10.06) between (68.912, 8.168) and (70.241, 10.352) reference; A62 r 3.35 centre (70, 5) between (68.912, 8.168) and (69.384, 1.707) reference; A63 r 2 centre (69.017, -0.259) between (71, 0) and (69.384, 1.707) reference; A64 r 74.6 centre (0, 0) between (74.6, 0) and (54.547, 50.89) reference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; 1 further point
  constraints: 4 point on circle, 2 centre point
extrude "Выдавливание18" cut sketch "Эскиз22" extent not by distance; stored distance "d93" = 12; taper "d94" = 0 deg
node "Твердое тело1"
node "РабОсь1"
node "РабОсь2"
node "РабОсь3"
node "РабОсь4"
node "РабОсь5"
node "Спроецированная петля1"
node "РабПлоскость1"
node "Спроецированная петля2"
node "Спроецированная петля3"
node "Спроецированная петля4"
node "Спроецированная петля7"
node "Спроецированная петля8"
node "Спроецированная петля9"
node "Спроецированная петля10"
node "Спроецированная петля11"
node "Спроецированная петля12"
node "Спроецированная петля13"
node "Спроецированная петля14"
other parameters: "d4" = 3, "d5" = 3
